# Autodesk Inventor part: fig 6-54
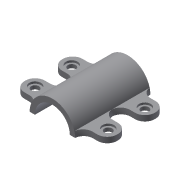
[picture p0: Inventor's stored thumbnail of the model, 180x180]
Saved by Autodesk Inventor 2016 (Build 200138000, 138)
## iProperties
Created: 2004-05
Part Number: fig 6-54
Document SubType Name: Modeling
Designer: CADCIM Technologies
Manufacturer: Standard
Standards Organization: Custom
Density: 1 g/cm^3
Material: Generic
Appearance: Default
Author: CADCIM Technologies
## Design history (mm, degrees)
node "Sketch1"
sketch "Sketch2"
  geometry: L1 (23.378, 0)-(17.996, 0); L2 (-17.996, 0)-(-23.378, 0); A1 r 23.378 centre (0, 0) between (23.378, 0) and (-23.378, 0); A2 r 17.996 centre (0, 0) between (17.996, 0) and (-17.996, 0)
  constraints: 4 end point, 4 point on circle, 2 centre point, 1 collinear, 1 horizontal
extrude "Extrusion1" new body sketch "Sketch2" stored distance "d0" = 38.75; taper "d1" = 0 deg
sketch "Sketch3"
  geometry: L1 (23.378, 0)-(17.996, 0); L2 (-17.996, 0)-(-23.378, 0) reference; L3 (-23.378, 0)-(-47.662, 0); L4 (-47.662, 0)-(-47.662, 5.722); L5 (-47.662, 5.722)-(-22.667, 5.722); A1 r 17.996 centre (0, 0) between (17.996, 0) and (-17.996, 0) reference; A2 r 23.378 centre (0, 0) between (23.378, 0) and (-23.378, 0) reference; 1 further point
  constraints: 10 end point, 5 point on circle, 2 centre point, 1 collinear, 1 horizontal, 1 midpoint, 1 parallel, 1 perpendicular, 3 other
extrude "Extrusion2" join sketch "Sketch3" stored distance "d2" = 21; taper "d3" = 0 deg
fillet "Fillet1" dims "d4" = 10
hole "Hole1" diameter "d7" = 8; stored, may be unused: countersink angle "d11" = 90 deg, drill point angle "d13" = 118 deg; dims "d5" = 10, "d6" = 10, "d8" = 6, "d9" = 12, "d10" = 2, "d12" = 12
fillet "Fillet2" dims "d14" = 9.5
mirror "Mirror1"
mirror "Mirror2"
body "Solid1"
